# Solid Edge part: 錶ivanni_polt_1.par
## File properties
Author: KULL
Template: Iso Metric Part.par
Last saved by: KULL
Revision: 3
Application: Solid Edge
Accuracy: 0,990
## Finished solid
Body 1: solid body, 43 faces, 89 edges, 48 vertices.
  Faces by surface: cylinder 20, torus 13, plane 10
  Edges by curve: circle 53, line 36
Bounding box of the edges (mm; curved faces can reach further): 3.000 x 3.000 x 6.400, from (-1.5, -1.5, -5) to (1.5, 1.5, 1.4).
Cylindrical faces by radius (mm): R0.05 x12, R0.1 x6, R0.7 x1, R1.5 x1
Toroidal faces (ring radius, tube radius in mm): R0.05 r0.05 x6, R0.15 r0.05 x6, R1.4 r0.1 x1
Planar faces by outward normal: +x 1, +z 2, -x 1, -z 2, oblique 4
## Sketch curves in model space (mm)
circle centre (0, 0, 0) radius 1
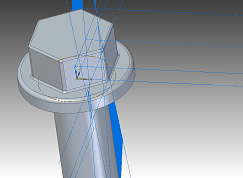
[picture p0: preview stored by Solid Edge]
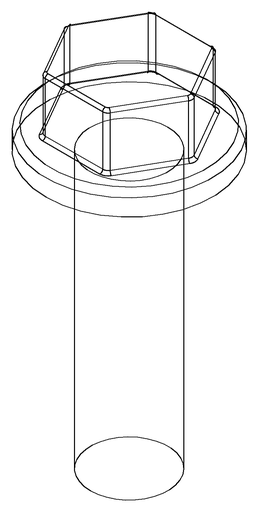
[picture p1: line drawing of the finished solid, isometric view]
